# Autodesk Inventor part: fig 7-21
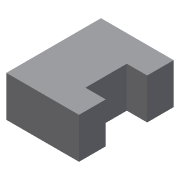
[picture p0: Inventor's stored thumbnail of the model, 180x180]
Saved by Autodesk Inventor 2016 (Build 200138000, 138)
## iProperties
Created: 2010-03
Part Number: fig 7-21
Document SubType Name: Modeling
Designer: CADSoft
Density: 1 g/cm^3
Material: Generic
Appearance: Default
Author: CADSoft
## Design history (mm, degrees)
sketch "Sketch1"
  geometry: L1 (-16.027, 20.205)-(19.726, 20.205); L2 (19.726, 20.205)-(19.726, -26.37); L3 (19.726, -26.37)-(-16.027, -26.37); L4 (-16.027, -26.37)-(-16.027, 20.205); 1 further point
  constraints: 8 end point, 2 parallel, 1 horizontal, 1 perpendicular
extrude "Extrusion1" new body sketch "Sketch1" distance "d0" = 20; taper "d1" = 0 deg
sketch "Sketch2"
  geometry: L1 (-20, 46.575)-(-20, 0) reference; L2 (0, 46.575)-(0, 0) reference; L3 (-20, 13.159)-(0, 13.159); L4 (0, 13.159)-(0, 33.527); L5 (0, 33.527)-(-20, 33.527); L6 (-20, 33.527)-(-20, 13.159); 1 further point
  constraints: 8 end point, 2 parallel, 2 point on line, 1 horizontal, 1 perpendicular
extrude "Extrusion2" cut sketch "Sketch2" distance "d2" = 10; taper "d3" = 0 deg
body "Solid1"
